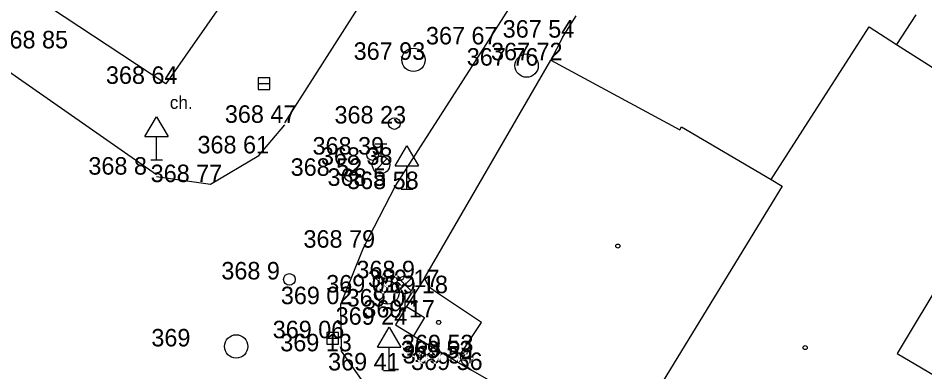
# Model space of a CAD drawing. Extents: x -688316 to -688024, y -973785 to -973591.
# Drawn here: x -688108.72 to -688069.85, y -973690.84 to -973675.68 of the extents above; entities that cross this region are included whole.
import ezdxf

# ---------------------------------------------------------------- set-up
doc = ezdxf.new("R2010")
doc.units = 0
for name, color, linetype in [('Vrstva 10', 7, 'Continuous'), ('Vrstva 11', 7, 'Continuous'), ('Vrstva 27', 7, 'Continuous'), ('Vrstva 28_Verejne osvetleni', 7, 'Continuous'), ('Vrstva 3', 7, 'Continuous'), ('Vrstva 33', 7, 'Continuous'), ('Vrstva 34', 7, 'Continuous'), ('Vrstva 40', 7, 'Continuous'), ('Vrstva 5', 7, 'Continuous'), ('Vrstva 58', 7, 'Continuous'), ('Vrstva 6', 7, 'Continuous')]:
    doc.layers.add(name, color=color, linetype=linetype)

# ---------------------------------------------------------------- blocks, each defined once
blk = doc.blocks.new('DZ')
at = {"layer": 'Vrstva 34'}
for p, q in [((-5, 10), (0, 18.5)), ((0, 18.5), (5, 10)), ((-5, 10), (5, 10)), ((0, 0), (0, 10)), ((-2.49, 0), (2.49, 0))]:
    blk.add_line(p, q, dxfattribs=at)
blk = doc.blocks.new('B_NESP')
at = {"layer": 'Vrstva 58'}
blk.add_circle((0, 0), 0.875, dxfattribs=at)
blk = doc.blocks.new('SV')
at = {"layer": 'Vrstva 28_Verejne osvetleni'}
blk.add_circle((0, 0), 2.5, dxfattribs=at)
blk = doc.blocks.new('SAK')
at = {"layer": 'Vrstva 27'}
blk.add_circle((0, 0), 5, dxfattribs=at)
blk = doc.blocks.new('HYP')
at = {"layer": 'Vrstva 28_Verejne osvetleni'}
for p, q in [((-2.5, 8.99), (2.5, 8.99)), ((0, 3.75), (0, 8.99)), ((-2.65, -2.65), (2.65, 2.65))]:
    blk.add_line(p, q, dxfattribs=at)
blk.add_circle((0, 0), 3.75, dxfattribs=at)
blk = doc.blocks.new('LAO')
at = {"layer": 'Vrstva 33'}
for p, q in [((-2.65, 14.16), (2.65, 8.85)), ((-2.65, 8.85), (2.65, 14.16)), ((0, 0), (0, 7.75))]:
    blk.add_line(p, q, dxfattribs=at)
blk.add_circle((0, 11.5), 3.75, dxfattribs=at)
blk = doc.blocks.new('VP')
at = {"layer": 'Vrstva 27'}
blk.add_line((-2.5, 0), (2.5, 0), dxfattribs=at)
blk.add_lwpolyline([(-2.5, -2.5), (2.5, -2.5), (2.5, 2.5), (-2.5, 2.5)], close=True, dxfattribs=at)
blk = doc.blocks.new('DKCH0')
at = {"layer": 'Vrstva 40'}
blk.add_text('ch.', height=5.5, dxfattribs=at).set_placement((-6.26, -3.04))

msp = doc.modelspace()

# ---------------------------------------------------------------- linework, layer by layer
at = {"layer": 'Vrstva 10'}
for p, q in [((-688088.66, -973676.81), (-688080.87, -973664.7)), ((-688102.38, -973678.5), (-688119.12, -973667.46)), ((-688097.29, -973680.17), (-688089.26, -973667.62)), ((-688096.69, -973670.33), (-688102.38, -973678.5)), ((-688111.87, -973676.05), (-688102.79, -973682.39)), ((-688092.54, -973682.87), (-688088.66, -973676.81))]:
    msp.add_line(p, q, dxfattribs=at)
for points in [[(-688102.79, -973682.476), (-688100.47, -973682.796), (-688098.4, -973681.566), (-688097.29, -973680.256)], [(-688093.66, -973691.65), (-688094.86, -973689.96), (-688094.89, -973687.94), (-688093.92, -973685.52), (-688092.54, -973682.87)]]:
    msp.add_lwpolyline(points, dxfattribs=at)
at = {"layer": 'Vrstva 11'}
msp.add_lwpolyline([(-688092.07, -973688.04), (-688091.3, -973688.51), (-688091.77, -973689.29)], dxfattribs=at)
at = {"layer": 'Vrstva 5'}
for p, q in [((-688070.24, -973675.54), (-688071.06, -973676.81)), ((-688076.44, -973682.6), (-688072.23, -973676.05)), ((-688072.23, -973676.05), (-688071.06, -973676.81)), ((-688085.38, -973676.52), (-688085.88, -973677.49)), ((-688071.06, -973676.81), (-688065.32, -973680.49)), ((-688085.88, -973677.49), (-688080.35, -973680.47)), ((-688080.35, -973680.47), (-688080.28, -973680.34)), ((-688080.28, -973680.34), (-688076.44, -973682.6)), ((-688065.32, -973680.49), (-688071.03, -973690.06)), ((-688075.97, -973682.88), (-688083.04, -973694.45)), ((-688076.44, -973682.6), (-688075.97, -973682.88)), ((-688091.77, -973689.29), (-688089.31, -973690.76)), ((-688071.03, -973690.06), (-688068.56, -973691.52))]:
    msp.add_line(p, q, dxfattribs=at)
for points in [[(-688085.18, -973693.12), (-688089.31, -973690.76), (-688089.67, -973690.48), (-688089.75, -973690.26), (-688089.7, -973690), (-688088.85, -973688.72), (-688090.74, -973687.47), (-688091.1, -973687.21), (-688091.3, -973686.83), (-688085.88, -973677.49)], [(-688091.3, -973686.83), (-688092.07, -973688.04), (-688092.54, -973688.82), (-688091.77, -973689.29)]]:
    msp.add_lwpolyline(points, dxfattribs=at)
at = {"layer": 'Vrstva 6'}
msp.add_line((-688085.38, -973676.52), (-688084.8, -973675.58), dxfattribs=at)

# ---------------------------------------------------------------- block references
at = {"layer": 'Vrstva 27', "xscale": 0.1, "yscale": 0.10000000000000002}
for name, p in [('SAK', (-688091.77, -973677.47)), ('SAK', (-688086.92, -973677.72)), ('VP', (-688098.184, -973678.485)), ('SAK', (-688092.89, -973687.44)), ('VP', (-688095.24, -973689.4)), ('SAK', (-688099.37, -973689.75))]:
    msp.add_blockref(name, p, dxfattribs=at)
at = {"layer": 'Vrstva 28_Verejne osvetleni', "xscale": 0.1, "yscale": 0.10000000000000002}
for name, p in [('SV', (-688092.59, -973680.2)), ('SV', (-688093.52, -973681.53)), ('HYP', (-688093.16, -973681.97)), ('SV', (-688094.47, -973682.44)), ('SV', (-688097.09, -973686.88))]:
    msp.add_blockref(name, p, dxfattribs=at)
at = {"layer": 'Vrstva 33', "xscale": 0.1, "yscale": 0.10000000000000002}
msp.add_blockref('LAO', (-688092.13, -973688.26), dxfattribs=at)
at = {"layer": 'Vrstva 34', "xscale": 0.1, "yscale": 0.10000000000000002}
for p in [(-688102.78, -973681.76), (-688102.78, -973681.76), (-688102.78, -973681.76), (-688102.78, -973681.76), (-688092.05, -973683.01), (-688092.05, -973683.01), (-688092.05, -973683.01), (-688092.05, -973683.01), (-688092.81, -973690.78), (-688092.81, -973690.78), (-688092.81, -973690.78), (-688092.81, -973690.78)]:
    msp.add_blockref('DZ', p, dxfattribs=at)
at = {"layer": 'Vrstva 40', "xscale": 0.1, "yscale": 0.10000000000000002}
msp.add_blockref('DKCH0', (-688101.59, -973679.268), dxfattribs=at)
at = {"layer": 'Vrstva 58', "xscale": 0.1, "yscale": 0.10000000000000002}
for p in [(-688083.01, -973685.45), (-688083.01, -973685.45), (-688083.01, -973685.45), (-688083.01, -973685.45), (-688090.69, -973688.72), (-688090.69, -973688.72), (-688090.69, -973688.72), (-688090.69, -973688.72), (-688074.98, -973689.8), (-688074.98, -973689.8), (-688074.98, -973689.8), (-688074.98, -973689.8)]:
    msp.add_blockref('B_NESP', p, dxfattribs=at)

# ---------------------------------------------------------------- texts
at = {"layer": 'Vrstva 3'}
for s, p in [('367 54 ', (-688087.946, -973676.52)), ('367 54 ', (-688087.946, -973676.52)), ('367 54 ', (-688087.946, -973676.52)), ('367 54 ', (-688087.946, -973676.52)), ('367 54 ', (-688087.946, -973676.52)), ('367 54 ', (-688087.946, -973676.52)), ('367 54 ', (-688087.946, -973676.52)), ('368 85 ', (-688109.646, -973676.98)), ('368 85 ', (-688109.646, -973676.98)), ('368 85 ', (-688109.646, -973676.98)), ('368 85 ', (-688109.646, -973676.98)), ('368 85 ', (-688109.646, -973676.98)), ('368 85 ', (-688109.646, -973676.98)), ('368 85 ', (-688109.646, -973676.98)), ('367 67 ', (-688091.235, -973676.81)), ('367 67 ', (-688091.235, -973676.81)), ('367 67 ', (-688091.235, -973676.81)), ('367 67 ', (-688091.235, -973676.81)), ('367 67 ', (-688091.235, -973676.81)), ('367 67 ', (-688091.235, -973676.81)), ('367 67 ', (-688091.235, -973676.81)), ('367 93 ', (-688094.336, -973677.47)), ('367 93 ', (-688094.336, -973677.47)), ('367 93 ', (-688094.336, -973677.47)), ('367 93 ', (-688094.336, -973677.47)), ('367 93 ', (-688094.336, -973677.47)), ('367 93 ', (-688094.336, -973677.47)), ('367 93 ', (-688094.336, -973677.47)), ('367 76 ', (-688089.486, -973677.72)), ('367 76 ', (-688089.486, -973677.72)), ('367 76 ', (-688089.486, -973677.72)), ('367 76 ', (-688089.486, -973677.72)), ('367 76 ', (-688089.486, -973677.72)), ('367 76 ', (-688089.486, -973677.72)), ('367 76 ', (-688089.486, -973677.72)), ('367 72 ', (-688088.446, -973677.49)), ('367 72 ', (-688088.446, -973677.49)), ('367 72 ', (-688088.446, -973677.49)), ('367 72 ', (-688088.446, -973677.49)), ('367 72 ', (-688088.446, -973677.49)), ('367 72 ', (-688088.446, -973677.49)), ('367 72 ', (-688088.446, -973677.49)), ('368 64 ', (-688104.955, -973678.5)), ('368 64 ', (-688104.955, -973678.5)), ('368 64 ', (-688104.955, -973678.5)), ('368 64 ', (-688104.955, -973678.5)), ('368 64 ', (-688104.955, -973678.5)), ('368 64 ', (-688104.955, -973678.5)), ('368 64 ', (-688104.955, -973678.5)), ('368 47 ', (-688099.856, -973680.17)), ('368 47 ', (-688099.856, -973680.17)), ('368 47 ', (-688099.856, -973680.17)), ('368 47 ', (-688099.856, -973680.17)), ('368 47 ', (-688099.856, -973680.17)), ('368 47 ', (-688099.856, -973680.17)), ('368 47 ', (-688099.856, -973680.17)), ('368 23 ', (-688095.156, -973680.2)), ('368 23 ', (-688095.156, -973680.2)), ('368 23 ', (-688095.156, -973680.2)), ('368 23 ', (-688095.156, -973680.2)), ('368 23 ', (-688095.156, -973680.2)), ('368 23 ', (-688095.156, -973680.2)), ('368 23 ', (-688095.156, -973680.2)), ('368 61 ', (-688101.03, -973681.48)), ('368 61 ', (-688101.03, -973681.48)), ('368 61 ', (-688101.03, -973681.48)), ('368 61 ', (-688101.03, -973681.48)), ('368 61 ', (-688101.03, -973681.48)), ('368 61 ', (-688101.03, -973681.48)), ('368 61 ', (-688101.03, -973681.48)), ('368 39 ', (-688096.098, -973681.53)), ('368 39 ', (-688096.098, -973681.53)), ('368 39 ', (-688096.098, -973681.53)), ('368 39 ', (-688096.098, -973681.53)), ('368 39 ', (-688096.098, -973681.53)), ('368 39 ', (-688096.098, -973681.53)), ('368 39 ', (-688096.098, -973681.53)), ('368 38 ', (-688095.738, -973681.97)), ('368 38 ', (-688095.738, -973681.97)), ('368 38 ', (-688095.738, -973681.97)), ('368 38 ', (-688095.738, -973681.97)), ('368 38 ', (-688095.738, -973681.97)), ('368 38 ', (-688095.738, -973681.97)), ('368 38 ', (-688095.738, -973681.97)), ('368 8  ', (-688105.707, -973682.39)), ('368 8  ', (-688105.707, -973682.39)), ('368 8  ', (-688105.707, -973682.39)), ('368 8  ', (-688105.707, -973682.39)), ('368 8  ', (-688105.707, -973682.39)), ('368 8  ', (-688105.707, -973682.39)), ('368 8  ', (-688105.707, -973682.39)), ('368 52 ', (-688097.036, -973682.44)), ('368 52 ', (-688097.036, -973682.44)), ('368 52 ', (-688097.036, -973682.44)), ('368 52 ', (-688097.036, -973682.44)), ('368 52 ', (-688097.036, -973682.44)), ('368 52 ', (-688097.036, -973682.44)), ('368 52 ', (-688097.036, -973682.44)), ('368 77 ', (-688103.036, -973682.71)), ('368 77 ', (-688103.036, -973682.71)), ('368 77 ', (-688103.036, -973682.71)), ('368 77 ', (-688103.036, -973682.71)), ('368 77 ', (-688103.036, -973682.71)), ('368 77 ', (-688103.036, -973682.71)), ('368 77 ', (-688103.036, -973682.71)), ('368 5  ', (-688095.457, -973682.87)), ('368 5  ', (-688095.457, -973682.87)), ('368 5  ', (-688095.457, -973682.87)), ('368 5  ', (-688095.457, -973682.87)), ('368 5  ', (-688095.457, -973682.87)), ('368 5  ', (-688095.457, -973682.87)), ('368 5  ', (-688095.457, -973682.87)), ('368 58 ', (-688094.616, -973683.01)), ('368 58 ', (-688094.616, -973683.01)), ('368 58 ', (-688094.616, -973683.01)), ('368 58 ', (-688094.616, -973683.01)), ('368 58 ', (-688094.616, -973683.01)), ('368 58 ', (-688094.616, -973683.01)), ('368 58 ', (-688094.616, -973683.01)), ('368 79 ', (-688096.486, -973685.52)), ('368 79 ', (-688096.486, -973685.52)), ('368 79 ', (-688096.486, -973685.52)), ('368 79 ', (-688096.486, -973685.52)), ('368 79 ', (-688096.486, -973685.52)), ('368 79 ', (-688096.486, -973685.52)), ('368 79 ', (-688096.486, -973685.52)), ('368 9  ', (-688100.007, -973686.88)), ('368 9  ', (-688100.007, -973686.88)), ('368 9  ', (-688100.007, -973686.88)), ('368 9  ', (-688100.007, -973686.88)), ('368 9  ', (-688100.007, -973686.88)), ('368 9  ', (-688100.007, -973686.88)), ('368 9  ', (-688100.007, -973686.88)), ('368 9  ', (-688094.217, -973686.83)), ('368 9  ', (-688094.217, -973686.83)), ('368 9  ', (-688094.217, -973686.83)), ('368 9  ', (-688094.217, -973686.83)), ('368 9  ', (-688094.217, -973686.83)), ('368 9  ', (-688094.217, -973686.83)), ('368 9  ', (-688094.217, -973686.83)), ('369 01 ', (-688095.511, -973687.44)), ('369 01 ', (-688095.511, -973687.44)), ('369 01 ', (-688095.511, -973687.44)), ('369 01 ', (-688095.511, -973687.44)), ('369 01 ', (-688095.511, -973687.44)), ('369 01 ', (-688095.511, -973687.44)), ('369 01 ', (-688095.511, -973687.44)), ('369 17 ', (-688093.721, -973687.21)), ('369 17 ', (-688093.721, -973687.21)), ('369 17 ', (-688093.721, -973687.21)), ('369 17 ', (-688093.721, -973687.21)), ('369 17 ', (-688093.721, -973687.21)), ('369 17 ', (-688093.721, -973687.21)), ('369 17 ', (-688093.721, -973687.21)), ('369 18 ', (-688093.361, -973687.47)), ('369 18 ', (-688093.361, -973687.47)), ('369 18 ', (-688093.361, -973687.47)), ('369 18 ', (-688093.361, -973687.47)), ('369 18 ', (-688093.361, -973687.47)), ('369 18 ', (-688093.361, -973687.47)), ('369 18 ', (-688093.361, -973687.47)), ('369 02 ', (-688097.456, -973687.94)), ('369 02 ', (-688097.456, -973687.94)), ('369 02 ', (-688097.456, -973687.94)), ('369 02 ', (-688097.456, -973687.94)), ('369 02 ', (-688097.456, -973687.94)), ('369 02 ', (-688097.456, -973687.94)), ('369 02 ', (-688097.456, -973687.94)), ('369 04 ', (-688094.636, -973688.04)), ('369 04 ', (-688094.636, -973688.04)), ('369 04 ', (-688094.636, -973688.04)), ('369 04 ', (-688094.636, -973688.04)), ('369 04 ', (-688094.636, -973688.04)), ('369 04 ', (-688094.636, -973688.04)), ('369 04 ', (-688094.636, -973688.04)), ('369 17 ', (-688093.921, -973688.51)), ('369 17 ', (-688093.921, -973688.51)), ('369 17 ', (-688093.921, -973688.51)), ('369 17 ', (-688093.921, -973688.51)), ('369 17 ', (-688093.921, -973688.51)), ('369 17 ', (-688093.921, -973688.51)), ('369 17 ', (-688093.921, -973688.51)), ('369 24 ', (-688095.106, -973688.82)), ('369 24 ', (-688095.106, -973688.82)), ('369 24 ', (-688095.106, -973688.82)), ('369 24 ', (-688095.106, -973688.82)), ('369 24 ', (-688095.106, -973688.82)), ('369 24 ', (-688095.106, -973688.82)), ('369 24 ', (-688095.106, -973688.82)), ('369 06 ', (-688097.806, -973689.4)), ('369 06 ', (-688097.806, -973689.4)), ('369 06 ', (-688097.806, -973689.4)), ('369 06 ', (-688097.806, -973689.4)), ('369 06 ', (-688097.806, -973689.4)), ('369 06 ', (-688097.806, -973689.4)), ('369 06 ', (-688097.806, -973689.4)), ('369    ', (-688103.007, -973689.75)), ('369    ', (-688103.007, -973689.75)), ('369    ', (-688103.007, -973689.75)), ('369    ', (-688103.007, -973689.75)), ('369    ', (-688103.007, -973689.75)), ('369    ', (-688103.007, -973689.75)), ('369    ', (-688103.007, -973689.75)), ('369 13 ', (-688097.481, -973689.96)), ('369 13 ', (-688097.481, -973689.96)), ('369 13 ', (-688097.481, -973689.96)), ('369 13 ', (-688097.481, -973689.96)), ('369 13 ', (-688097.481, -973689.96)), ('369 13 ', (-688097.481, -973689.96)), ('369 13 ', (-688097.481, -973689.96)), ('369 53 ', (-688092.316, -973690.26)), ('369 53 ', (-688092.316, -973690.26)), ('369 53 ', (-688092.316, -973690.26)), ('369 53 ', (-688092.316, -973690.26)), ('369 53 ', (-688092.316, -973690.26)), ('369 53 ', (-688092.316, -973690.26)), ('369 53 ', (-688092.316, -973690.26)), ('369 53 ', (-688092.266, -973690)), ('369 53 ', (-688092.266, -973690)), ('369 53 ', (-688092.266, -973690)), ('369 53 ', (-688092.266, -973690)), ('369 53 ', (-688092.266, -973690)), ('369 53 ', (-688092.266, -973690)), ('369 53 ', (-688092.266, -973690)), ('369 54 ', (-688092.236, -973690.48)), ('369 54 ', (-688092.236, -973690.48)), ('369 54 ', (-688092.236, -973690.48)), ('369 54 ', (-688092.236, -973690.48)), ('369 54 ', (-688092.236, -973690.48)), ('369 54 ', (-688092.236, -973690.48)), ('369 54 ', (-688092.236, -973690.48)), ('369 41 ', (-688095.431, -973690.78)), ('369 41 ', (-688095.431, -973690.78)), ('369 41 ', (-688095.431, -973690.78)), ('369 41 ', (-688095.431, -973690.78)), ('369 41 ', (-688095.431, -973690.78)), ('369 41 ', (-688095.431, -973690.78)), ('369 41 ', (-688095.431, -973690.78)), ('369 56 ', (-688091.876, -973690.76)), ('369 56 ', (-688091.876, -973690.76)), ('369 56 ', (-688091.876, -973690.76)), ('369 56 ', (-688091.876, -973690.76)), ('369 56 ', (-688091.876, -973690.76)), ('369 56 ', (-688091.876, -973690.76)), ('369 56 ', (-688091.876, -973690.76))]:
    msp.add_text(s, height=0.75, dxfattribs=at).set_placement(p)

doc.saveas('drawing.dxf')
